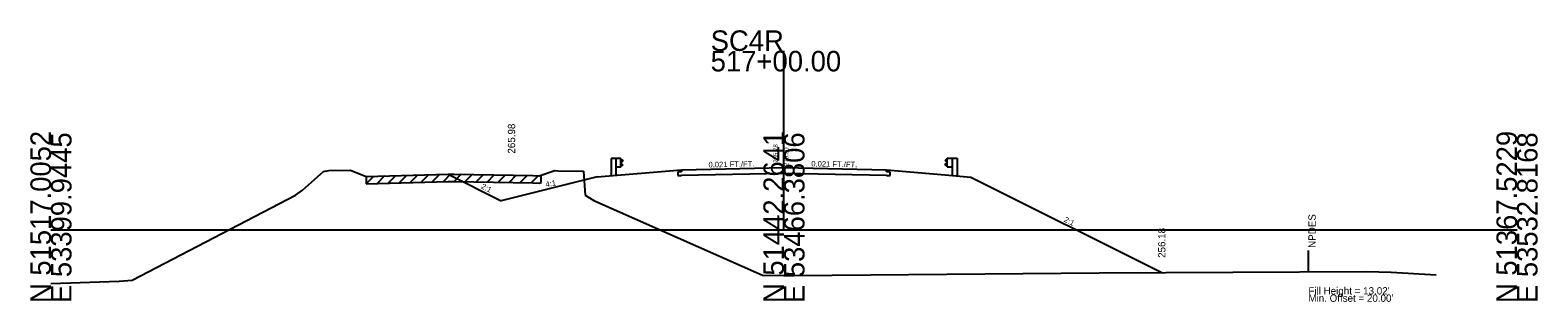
# Model space of a CAD drawing. Extents: x 7498 to 13027, y 90095 to 109625.
# Drawn here: x 8521.2 to 8726.8, y 107095.3 to 107132.5 of the extents above; entities that cross this region are included whole.
import ezdxf

# ---------------------------------------------------------------- set-up
doc = ezdxf.new("R2010")
doc.units = 0
for name, color, linetype in [('Level 10', 7, 'Continuous'), ('Level 11', 7, 'Continuous'), ('Level 12', 7, 'Continuous'), ('Level 24', 7, 'Continuous'), ('Level 32', 7, 'Continuous'), ('Level 33', 7, 'Continuous'), ('Level 50', 7, 'Continuous'), ('Level 55', 7, 'Continuous'), ('Level 59', 7, 'Continuous'), ('Level 6', 7, 'Continuous'), ('Level 60', 7, 'Continuous'), ('Level 61', 7, 'Continuous'), ('Level 63', 7, 'Continuous'), ('Level 7', 7, 'Continuous')]:
    doc.layers.add(name, color=color, linetype=linetype)

msp = doc.modelspace()

# ---------------------------------------------------------------- linework, layer by layer
at = {"layer": 'Level 11'}
for p, q in [((8609.99, 107113.07), (8609.49, 107113.05)), ((8609.49, 107113.05), (8609.49, 107112.57)), ((8609.99, 107113.37), (8609.99, 107113.07)), ((8637.99, 107113.07), (8637.99, 107113.37)), ((8638.49, 107113.05), (8637.99, 107113.07)), ((8638.49, 107112.57), (8638.49, 107113.05)), ((8609.49, 107112.57), (8609.99, 107112.59)), ((8637.99, 107112.59), (8638.49, 107112.57))]:
    msp.add_line(p, q, dxfattribs=at)
at = {"layer": 'Level 12'}
for p, q in [((8623.99, 107112.88), (8609.99, 107112.59)), ((8637.99, 107112.59), (8623.99, 107112.88))]:
    msp.add_line(p, q, dxfattribs=at)
at = {"layer": 'Level 24'}
for p, q in [((8601.07, 107114.9), (8600.4, 107114.9)), ((8600.4, 107114.9), (8600.4, 107112.49)), ((8601.74, 107114.9), (8601.07, 107114.9)), ((8601.07, 107114.9), (8601.07, 107112.56)), ((8601.74, 107113.74), (8601.74, 107114.9)), ((8601.74, 107114.83), (8602.01, 107114.63)), ((8646.26, 107114.88), (8645.99, 107114.68)), ((8646.26, 107113.78), (8646.26, 107114.95)), ((8646.26, 107114.95), (8646.93, 107114.95)), ((8646.93, 107114.95), (8646.93, 107112.6)), ((8646.93, 107114.95), (8647.6, 107114.95)), ((8647.6, 107114.95), (8647.6, 107112.54)), ((8601.74, 107113.74), (8601.07, 107113.74)), ((8602.01, 107114.58), (8601.74, 107114.38)), ((8602.01, 107114.06), (8601.74, 107114.26)), ((8601.74, 107113.81), (8602.01, 107114.01)), ((8602.01, 107114.63), (8602.01, 107114.58)), ((8602.01, 107114.01), (8602.01, 107114.06)), ((8645.99, 107114.68), (8645.99, 107114.63)), ((8645.99, 107114.63), (8646.26, 107114.43)), ((8645.99, 107114.1), (8646.26, 107114.3)), ((8645.99, 107114.05), (8645.99, 107114.1)), ((8646.26, 107113.85), (8645.99, 107114.05)), ((8646.26, 107113.78), (8646.93, 107113.78))]:
    msp.add_line(p, q, dxfattribs=at)
at = {"layer": 'Level 55'}
msp.add_line((8695.53, 107099.33), (8695.53, 107102.33), dxfattribs=at)
at = {"layer": 'Level 59'}
for p, q in [((8609.99, 107113.37), (8623.99, 107113.66)), ((8623.99, 107113.66), (8637.99, 107113.37))]:
    msp.add_line(p, q, dxfattribs=at)
at = {"layer": 'Level 6'}
for p, q in [((8598.49, 107112.41), (8609.99, 107113.37)), ((8637.99, 107113.37), (8645.99, 107112.7)), ((8645.99, 107112.7), (8649.49, 107112.35))]:
    msp.add_line(p, q, dxfattribs=at)
at = {"layer": 'Level 60'}
for p, q in [((8558.32, 107110.59), (8561.17, 107113.15)), ((8561.17, 107113.15), (8561.91, 107113.26)), ((8561.91, 107113.26), (8564.86, 107113.31)), ((8564.86, 107113.31), (8567, 107112.45)), ((8567, 107112.45), (8578.19, 107112.76)), ((8578.19, 107112.76), (8579.01, 107112.78)), ((8579.01, 107112.78), (8589.75, 107112.57)), ((8590.6, 107112.55), (8592.71, 107113.29)), ((8592.71, 107113.29), (8593.14, 107113.21)), ((8593.14, 107113.21), (8596.66, 107113.17)), ((8596.66, 107113.17), (8596.85, 107109.91)), ((8589.75, 107112.57), (8590.6, 107112.55)), ((8535.06, 107098.3), (8557.37, 107109.92)), ((8557.37, 107109.92), (8558.32, 107110.59)), ((8596.85, 107109.91), (8598.05, 107109.19)), ((8598.05, 107109.19), (8621.06, 107098.98)), ((8621.06, 107098.98), (8623.99, 107098.93)), ((8623.99, 107098.93), (8625.39, 107098.91)), ((8625.39, 107098.91), (8666.99, 107099.29)), ((8666.99, 107099.29), (8703.45, 107099.48)), ((8703.45, 107099.48), (8706.83, 107099.38)), ((8706.83, 107099.38), (8712.98, 107099.01)), ((8523.99, 107097.85), (8533.29, 107098.15)), ((8533.29, 107098.15), (8535.06, 107098.3))]:
    msp.add_line(p, q, dxfattribs=at)
at = {"layer": 'Level 61'}
for p, q in [((8578.51, 107112.77), (8577.48, 107111.74)), ((8579.96, 107112.76), (8578.98, 107111.78)), ((8568, 107112.47), (8566.98, 107111.45)), ((8566.98, 107112.45), (8566.98, 107111.45)), ((8566.98, 107111.45), (8567, 107111.45)), ((8567, 107111.45), (8578.19, 107111.76)), ((8569.51, 107112.52), (8568.48, 107111.49)), ((8571.01, 107112.56), (8569.98, 107111.53)), ((8572.51, 107112.6), (8571.48, 107111.57)), ((8574.01, 107112.64), (8572.98, 107111.61)), ((8575.51, 107112.69), (8574.48, 107111.66)), ((8577.01, 107112.73), (8575.98, 107111.7)), ((8578.19, 107111.76), (8579.01, 107111.78)), ((8579.01, 107111.78), (8589.75, 107111.57)), ((8581.46, 107112.73), (8580.48, 107111.75)), ((8582.96, 107112.7), (8581.98, 107111.72)), ((8584.46, 107112.68), (8583.48, 107111.69)), ((8585.96, 107112.65), (8584.98, 107111.67)), ((8587.46, 107112.62), (8586.48, 107111.64)), ((8588.96, 107112.59), (8587.98, 107111.61)), ((8590.45, 107112.55), (8589.48, 107111.58)), ((8589.75, 107111.57), (8590.6, 107111.55)), ((8590.6, 107111.55), (8590.85, 107111.64)), ((8590.85, 107111.64), (8590.85, 107112.64))]:
    msp.add_line(p, q, dxfattribs=at)
at = {"layer": 'Level 63'}
for p, q in [((8623.99, 107105.16), (8623.99, 107129.61)), ((8523.99, 107105.16), (8623.99, 107105.16)), ((8623.99, 107105.16), (8723.99, 107105.16))]:
    msp.add_line(p, q, dxfattribs=at)
at = {"layer": 'Level 7'}
for p, q in [((8578.16, 107112.76), (8585.41, 107109.14)), ((8598.49, 107112.41), (8585.41, 107109.14)), ((8649.49, 107112.35), (8675.53, 107099.33))]:
    msp.add_line(p, q, dxfattribs=at)

# ---------------------------------------------------------------- texts
at = {"layer": 'Level 10'}
msp.add_text('255.78', height=0.6, rotation=90, dxfattribs=at).set_placement((8623.14, 107114.33))
at = {"layer": 'Level 32'}
for s, rotation, p in [('0.021 FT./FT.', 1.1916, (8613.7, 107113.69)), ('0.021 FT./FT.', 358.8084, (8627.71, 107113.83)), ('2:1', 333.435, (8582.6, 107110.87)), ('4:1', 9.4623, (8591.52, 107111)), ('2:1', 333.435, (8662.11, 107106.32))]:
    msp.add_text(s, height=0.75, rotation=rotation, dxfattribs=at).set_placement(p)
at = {"layer": 'Level 33'}
for s, p in [('265.98', (8587.32, 107115.58)), ('256.18', (8676.03, 107101.33))]:
    msp.add_text(s, height=1, rotation=90, dxfattribs=at).set_placement(p)
at = {"layer": 'Level 50'}
msp.add_text(' NPDES', height=1, rotation=90, dxfattribs=at).set_placement((8696.53, 107102.33))
for s, p in [("Fill Height = 13.02' ", (8695.53, 107096.33)), ("Min. Offset = 20.00' ", (8695.53, 107095.33))]:
    msp.add_text(s, height=1, dxfattribs=at).set_placement(p)
at = {"layer": 'Level 59'}
msp.add_text(' 270.50', height=0.6, rotation=90, dxfattribs=at).set_placement((8624.59, 107113.66))
at = {"layer": 'Level 63'}
for s, p in [('SC4R', (8613.99, 107129.61)), ('517+00.00', (8613.99, 107126.81))]:
    msp.add_text(s, height=2.8, dxfattribs=at).set_placement(p)
for s, p in [('N 51517.0052', (8523.99, 107095.16)), ('E 53399.9445', (8526.79, 107095.16)), ('N 51442.2641', (8623.99, 107095.16)), ('E 53466.3806', (8626.79, 107095.16)), ('N 51367.5229', (8723.99, 107095.16)), ('E 53532.8168', (8726.79, 107095.16))]:
    msp.add_text(s, height=2.8, rotation=90, dxfattribs=at).set_placement(p)

doc.saveas('drawing.dxf')
